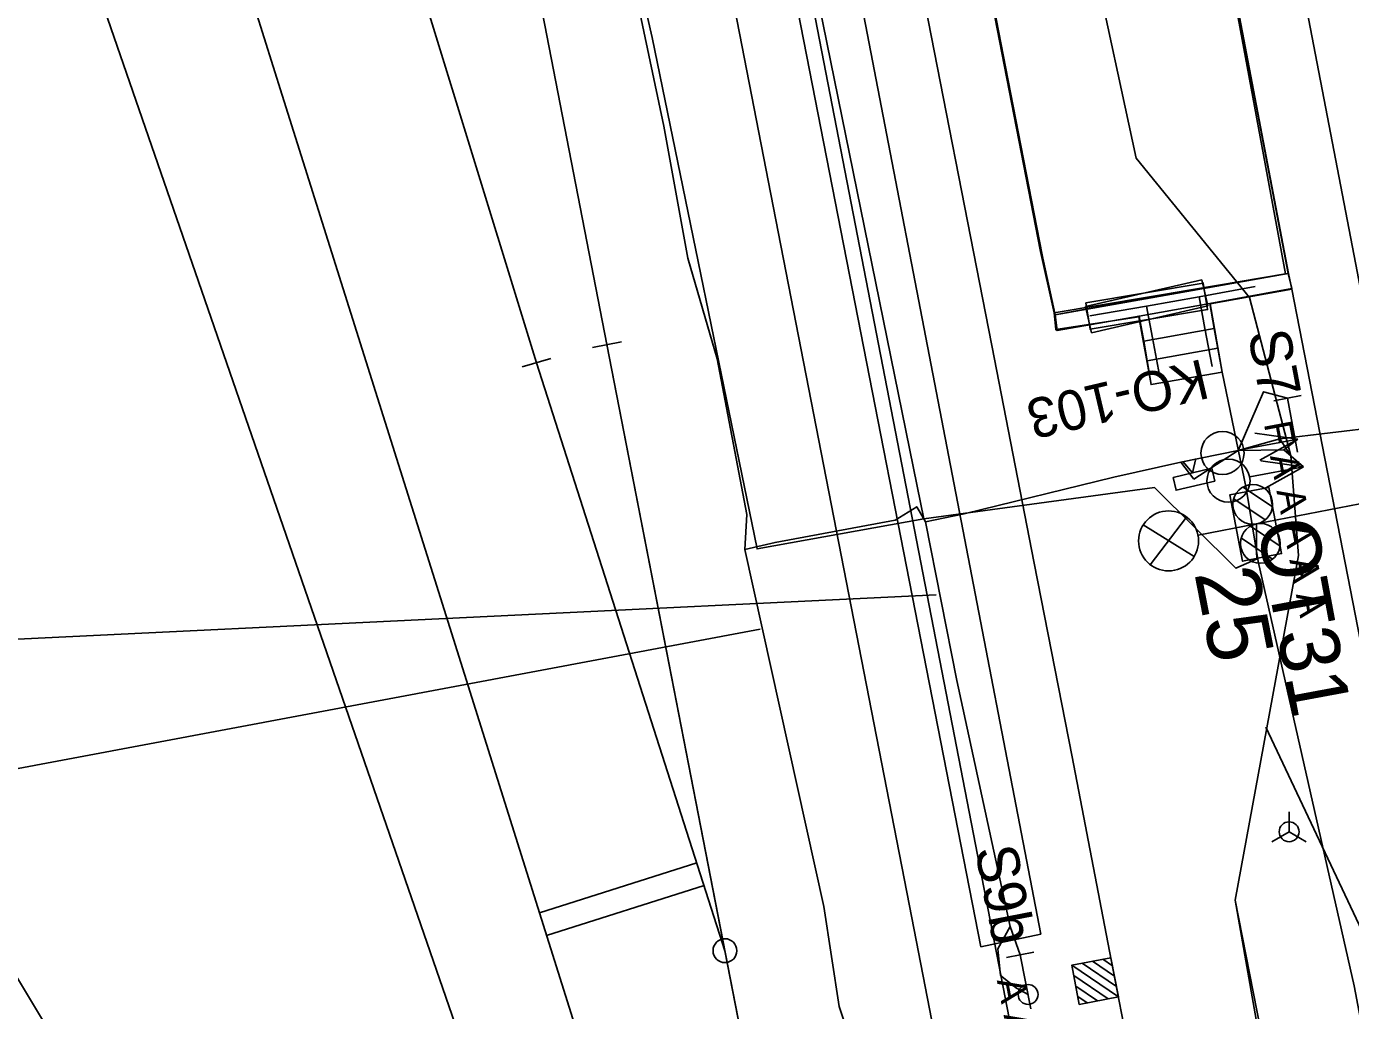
# Model space of a CAD drawing. Extents: x -545736 to -544888, y -1122892 to -1119128.
# Drawn here: x -545168.18 to -545134.88, y -1122258.5 to -1122233.75 of the extents above; entities that cross this region are included whole.
import ezdxf

# ---------------------------------------------------------------- set-up
doc = ezdxf.new("R2010")
doc.units = 0
for name, color, linetype in [('osvětlené plochy-hodnota-obrys', 7, 'Continuous'), ('Podbarveni_Nastupiste', 7, 'Continuous'), ('Vrstva 1', 7, 'Continuous'), ('Vrstva 1 - Koleje', 7, 'Continuous'), ('Vrstva 11 - Trakce', 7, 'Continuous'), ('Vrstva 12 - Trakce zaklady', 7, 'Continuous'), ('Vrstva 13', 7, 'Continuous'), ('Vrstva 14_zastreseni a nastupiste', 7, 'Continuous'), ('Vrstva 16_plochy', 7, 'Continuous'), ('Vrstva 17_ploty - zabradli', 7, 'Continuous'), ('Vrstva 2', 7, 'Continuous'), ('Vrstva 23 - PHS - pozemni - schody - eskalatory', 7, 'Continuous'), ('Vrstva 25', 7, 'Continuous'), ('Vrstva 26', 7, 'Continuous'), ('Vrstva 27', 7, 'Continuous'), ('Vrstva 28 - zabzar', 7, 'Continuous'), ('Vrstva 3 - Lisy - Pocitaci body', 7, 'Continuous'), ('Vrstva 31', 7, 'Continuous'), ('Vrstva 35', 7, 'Continuous'), ('Vrstva 4 - Teren - stezky - prechody - plochy', 7, 'Continuous'), ('Vrstva 6 - Navesti', 7, 'Continuous'), ('Vrstva 63', 7, 'Continuous'), ('Vrstva 7', 7, 'Continuous')]:
    doc.layers.add(name, color=color, linetype=linetype)

msp = doc.modelspace()

# ---------------------------------------------------------------- linework, layer by layer
at = {"layer": 'osvětlené plochy-hodnota-obrys'}
msp.add_lwpolyline([(-545132.033, -1122317.745), (-545201.844, -1121957.194), (-545188.779, -1121954.655), (-545199.189, -1121901.389)], dxfattribs=at)
at = {"layer": 'Podbarveni_Nastupiste'}
for points in [[(-545198.773, -1121951.627), (-545191.691, -1121987.986), (-545182.222, -1122036.609), (-545172.438, -1122086.699), (-545162.999, -1122135.094), (-545153.274, -1122184.937), (-545142.505, -1122240.181), (-545142.306, -1122241.006)], [(-545136.516, -1122239.976), (-545138.799, -1122227.627), (-545147.465, -1122183.189), (-545157.09, -1122133.892), (-545166.638, -1122084.896), (-545171.447, -1122060.234), (-545173.829, -1122047.49), (-545174.717, -1122041.983)], [(-545142.306, -1122241.006), (-545139.39, -1122240.46), (-545136.516, -1122239.976)]]:
    msp.add_lwpolyline(points, dxfattribs=at)
at = {"layer": 'Vrstva 1'}
for points in [[(-545148.11, -1122269.864), (-545153.579, -1122241.752), (-545157.606, -1122221.016), (-545162.537, -1122195.725), (-545168.276, -1122166.312), (-545171.822, -1122147.996)], [(-545134.901, -1122312.911), (-545138.046, -1122296.967), (-545143.24, -1122269.949), (-545145.914, -1122256.175), (-545149.457, -1122237.965), (-545152.971, -1122219.909), (-545157.547, -1122196.44), (-545162.223, -1122172.446), (-545166.848, -1122148.879)], [(-545150.613, -1122256.998), (-545155.352, -1122242.208), (-545159.254, -1122229.505), (-545164.277, -1122213.17), (-545171.316, -1122189.563), (-545175.304, -1122173.781), (-545177.735, -1122161.806)], [(-545144.042, -1122290.699), (-545148.294, -1122278.255), (-545152.413, -1122265.168), (-545157.625, -1122248.574), (-545161.751, -1122235.479), (-545164.693, -1122226.098), (-545170.107, -1122208.853), (-545174.307, -1122195.178), (-545174.307, -1122195.178), (-545179.326, -1122176.026), (-545182.038, -1122162.981)], [(-545137.784, -1122322.523), (-545141.85, -1122311.027), (-545145.756, -1122300.605), (-545151.826, -1122286.809), (-545158.816, -1122273.694), (-545169.453, -1122255.952), (-545171.427, -1122252.524)]]:
    msp.add_lwpolyline(points, dxfattribs=at)
at = {"layer": 'Vrstva 1 - Koleje'}
for points in [[(-545176.383, -1122075.263), (-545174.481, -1122085.012), (-545172.568, -1122094.81), (-545170.661, -1122104.603), (-545170.158, -1122107.18), (-545168.724, -1122114.524), (-545166.809, -1122124.368), (-545164.912, -1122134.097), (-545162.998, -1122143.914), (-545161.094, -1122153.659), (-545159.194, -1122163.404), (-545157.278, -1122173.216), (-545155.337, -1122183.16), (-545153.457, -1122192.791), (-545151.544, -1122202.612), (-545149.632, -1122212.391), (-545147.716, -1122222.215), (-545145.801, -1122232.042), (-545143.903, -1122241.777), (-545142.834, -1122247.253), (-545141.885, -1122252.118), (-545140.814, -1122257.667), (-545140.289, -1122260.383)], [(-545142.334, -1122200.685), (-545140.419, -1122210.525), (-545138.503, -1122220.353), (-545136.566, -1122230.271), (-545134.71, -1122239.954), (-545133.946, -1122244.067), (-545133.443, -1122246.77), (-545131.615, -1122256.726), (-545129.899, -1122266.071), (-545129.007, -1122270.907), (-545127.892, -1122277.019), (-545124.281, -1122296.703), (-545123.116, -1122309.448)]]:
    msp.add_lwpolyline(points, dxfattribs=at)
at = {"layer": 'Vrstva 11 - Trakce'}
for p, q in [((-545137.244, -1122246.262), (-545105.83, -1122240.196)), ((-545137.585, -1122245.337), (-545136.845, -1122245.836)), ((-545137.817, -1122245.633), (-545137.031, -1122246.163)), ((-545137.396, -1122246.321), (-545136.654, -1122246.821)), ((-545137.627, -1122246.619), (-545136.842, -1122247.146))]:
    msp.add_line(p, q, dxfattribs=at)
for centre in [(-545137.34, -1122245.771), (-545137.148, -1122246.753)]:
    msp.add_circle(centre, 0.5, dxfattribs=at)
at = {"layer": 'Vrstva 12 - Trakce zaklady'}
for p, q in [((-545137.92, -1122245.535), (-545136.939, -1122245.343)), ((-545136.614, -1122247.008), (-545137.595, -1122247.2))]:
    msp.add_line(p, q, dxfattribs=at)
for points in [[(-545136.939, -1122245.343), (-545136.614, -1122247.008), (-545137.595, -1122247.2), (-545137.92, -1122245.535), (-545136.939, -1122245.343)], [(-545137.92, -1122245.535), (-545137.92, -1122245.535), (-545137.595, -1122247.2), (-545137.595, -1122247.2)], [(-545136.939, -1122245.343), (-545136.939, -1122245.343), (-545136.614, -1122247.008), (-545136.614, -1122247.008)]]:
    msp.add_lwpolyline(points, dxfattribs=at)
at = {"layer": 'Vrstva 13'}
for p, q in [((-545136.447, -1122239.964), (-545136.443, -1122239.964)), ((-545136.355, -1122240.354), (-545136.356, -1122240.337)), ((-545142.306, -1122241.006), (-545142.337, -1122240.955)), ((-545142.292, -1122241.376), (-545142.261, -1122241.397))]:
    msp.add_line(p, q, dxfattribs=at)
msp.add_lwpolyline([(-545139.377, -1122240.485), (-545142.306, -1122241.006), (-545142.261, -1122241.397), (-545140.197, -1122241.033), (-545138.421, -1122240.72), (-545136.356, -1122240.337), (-545136.447, -1122239.964)], close=True, dxfattribs=at)
for points in [[(-545138.421, -1122240.72), (-545138.41, -1122240.724), (-545136.355, -1122240.354), (-545136.443, -1122239.964)], [(-545142.337, -1122240.955), (-545142.292, -1122241.376), (-545140.203, -1122241.053), (-545140.197, -1122241.033)]]:
    msp.add_lwpolyline(points, dxfattribs=at)
at = {"layer": 'Vrstva 14_zastreseni a nastupiste'}
for p, q in [((-545136.443, -1122239.964), (-545136.447, -1122239.964)), ((-545142.337, -1122240.955), (-545142.306, -1122241.006))]:
    msp.add_line(p, q, dxfattribs=at)
for points in [[(-545174.372, -1122076.877), (-545172.469, -1122086.648), (-545170.563, -1122096.424), (-545168.648, -1122106.251), (-545166.742, -1122116.03), (-545164.832, -1122125.805), (-545162.92, -1122135.608), (-545161.017, -1122145.366), (-545159.102, -1122155.184), (-545157.19, -1122164.981), (-545155.268, -1122174.806), (-545153.362, -1122184.59), (-545151.463, -1122194.367), (-545149.557, -1122204.15), (-545147.636, -1122213.972), (-545145.723, -1122223.752), (-545143.824, -1122233.506), (-545142.674, -1122239.408), (-545142.337, -1122240.955)], [(-545174.341, -1122076.928), (-545172.438, -1122086.699), (-545170.532, -1122096.475), (-545168.617, -1122106.302), (-545166.711, -1122116.081), (-545164.801, -1122125.856), (-545162.889, -1122135.659), (-545160.986, -1122145.417), (-545159.071, -1122155.235), (-545157.159, -1122165.032), (-545155.237, -1122174.857), (-545153.331, -1122184.641), (-545151.432, -1122194.418), (-545149.526, -1122204.201), (-545147.605, -1122214.023), (-545145.692, -1122223.803), (-545143.793, -1122233.557), (-545142.643, -1122239.459), (-545142.306, -1122241.006)], [(-545142.306, -1122241.006), (-545139.377, -1122240.485), (-545136.447, -1122239.964), (-545138.244, -1122230.551), (-545140.147, -1122220.747), (-545142.055, -1122210.937), (-545143.965, -1122201.145), (-545145.873, -1122191.373), (-545147.779, -1122181.574), (-545149.696, -1122171.781), (-545151.614, -1122161.976), (-545153.523, -1122152.193), (-545155.434, -1122142.369), (-545156.586, -1122136.479), (-545158.487, -1122126.724), (-545160.396, -1122116.93), (-545162.308, -1122107.103), (-545164.211, -1122097.329), (-545166.122, -1122087.54), (-545168.031, -1122077.749)], [(-545142.337, -1122240.955), (-545136.443, -1122239.964), (-545138.231, -1122230.556), (-545140.134, -1122220.752), (-545142.042, -1122210.942), (-545143.952, -1122201.15), (-545145.86, -1122191.378), (-545147.766, -1122181.579), (-545149.683, -1122171.786), (-545151.601, -1122161.981), (-545153.51, -1122152.198), (-545155.421, -1122142.374), (-545156.573, -1122136.484), (-545158.474, -1122126.729), (-545160.383, -1122116.935), (-545162.295, -1122107.108), (-545164.198, -1122097.334), (-545166.109, -1122087.545), (-545168.018, -1122077.754)]]:
    msp.add_lwpolyline(points, dxfattribs=at)
at = {"layer": 'Vrstva 16_plochy'}
msp.add_lwpolyline([(-545143.965, -1122201.145), (-545142.055, -1122210.937), (-545140.147, -1122220.747), (-545138.244, -1122230.551), (-545136.447, -1122239.964), (-545139.377, -1122240.485), (-545142.306, -1122241.006), (-545142.643, -1122239.459), (-545143.793, -1122233.557), (-545145.692, -1122223.803), (-545147.605, -1122214.023), (-545149.526, -1122204.201)], dxfattribs=at)
at = {"layer": 'Vrstva 17_ploty - zabradli'}
for p, q in [((-545140.008, -1122240.787), (-545138.691, -1122240.547)), ((-545138.691, -1122240.547), (-545137.282, -1122240.291)), ((-545141.434, -1122241.029), (-545140.008, -1122240.787))]:
    msp.add_line(p, q, dxfattribs=at)
for points in [[(-545138.357, -1122242.305), (-545138.545, -1122241.343), (-545138.691, -1122240.547)], [(-545140.008, -1122240.787), (-545139.86, -1122241.584), (-545139.687, -1122242.517)]]:
    msp.add_lwpolyline(points, dxfattribs=at)
at = {"layer": 'Vrstva 2'}
for p, q in [((-545153.211, -1122241.68), (-545153.947, -1122241.824)), ((-545155.713, -1122242.311), (-545154.991, -1122242.105)), ((-545150.613, -1122256.998), (-545155.352, -1122242.208))]:
    msp.add_line(p, q, dxfattribs=at)
msp.add_lwpolyline([(-545148.11, -1122269.864), (-545150.613, -1122256.998), (-545153.579, -1122241.752)], dxfattribs=at)
msp.add_circle((-545150.613, -1122256.998), 0.3, dxfattribs=at)
at = {"layer": 'Vrstva 23 - PHS - pozemni - schody - eskalatory'}
for p, q in [((-545138.41, -1122240.724), (-545138.421, -1122240.72)), ((-545140.079, -1122241.663), (-545138.307, -1122241.343))]:
    msp.add_line(p, q, dxfattribs=at)
for points in [[(-545141.392, -1122241.453), (-545141.543, -1122240.795), (-545138.624, -1122240.123), (-545138.472, -1122240.781)], [(-545141.541, -1122240.701), (-545141.429, -1122241.368), (-545138.475, -1122240.871), (-545138.587, -1122240.204)]]:
    msp.add_lwpolyline(points, close=True, dxfattribs=at)
for points in [[(-545138.41, -1122240.724), (-545138.109, -1122242.449), (-545139.898, -1122242.758), (-545140.203, -1122241.053)], [(-545138.109, -1122242.449), (-545138.307, -1122241.343), (-545138.421, -1122240.72), (-545140.197, -1122241.033)], [(-545139.898, -1122242.758), (-545140.079, -1122241.663), (-545140.197, -1122241.033), (-545140.203, -1122241.053)], [(-545139.996, -1122242.163), (-545138.217, -1122241.843)]]:
    msp.add_lwpolyline(points, dxfattribs=at)
at = {"layer": 'Vrstva 25'}
for p, q in [((-545139.916, -1122247.289), (-545139.003, -1122246.089)), ((-545140.095, -1122246.289), (-545138.811, -1122247.081)), ((-545138.716, -1122246.549), (-545137.244, -1122246.262))]:
    msp.add_line(p, q, dxfattribs=at)
msp.add_circle((-545139.457, -1122246.691), 0.754, dxfattribs=at)
at = {"layer": 'Vrstva 26'}
for points in [[(-545155.064, -1122220.881), (-545155.129, -1122222.319), (-545152.44, -1122234.026), (-545149.806, -1122246.893), (-545145.608, -1122246.135), (-545139.808, -1122245.349), (-545137.763, -1122247.379), (-545137.229, -1122247.143), (-545137.25, -1122247.012), (-545137.244, -1122246.262)], [(-545170.317, -1122221.476), (-545155.427, -1122264.551), (-545158.826, -1122266.782), (-545159.569, -1122267.253)], [(-545125.523, -1122226.836), (-545126.199, -1122227.617), (-545126.923, -1122226.469), (-545128.585, -1122223.338), (-545130.219, -1122223.203), (-545149.701, -1122226.017), (-545149.372, -1122227.635), (-545145.776, -1122245.312), (-545145.608, -1122246.135)], [(-545149.806, -1122246.893), (-545145.608, -1122246.135), (-545139.808, -1122245.349)]]:
    msp.add_lwpolyline(points, dxfattribs=at)
at = {"layer": 'Vrstva 27'}
for p, q in [((-545139.344, -1122245.096), (-545139.342, -1122245.092)), ((-545142.985, -1122258.125), (-545142.995, -1122258.075))]:
    msp.add_line(p, q, dxfattribs=at)
msp.add_lwpolyline([(-545139.345, -1122245.093), (-545138.372, -1122244.863), (-545138.295, -1122245.187), (-545139.268, -1122245.417)], close=True, dxfattribs=at)
msp.add_lwpolyline([(-545139.097, -1122244.692), (-545138.858, -1122244.978), (-545138.773, -1122244.615)], dxfattribs=at)
msp.add_circle((-545142.99, -1122258.1), 0.25, dxfattribs=at)
at = {"layer": 'Vrstva 28 - zabzar'}
for points in [[(-545136.66, -1122244.12), (-545132.86, -1122243.67), (-545132.22, -1122243.53), (-545132.12, -1122242.5), (-545134.24, -1122231), (-545136.38, -1122218.29), (-545140.4, -1122198.68), (-545141.27, -1122195.81), (-545142.27, -1122190.49), (-545142.25, -1122189.04)], [(-545150.11, -1122246.91), (-545150.06, -1122246.03), (-545150.81, -1122242.11), (-545151.55, -1122239.58), (-545152.15, -1122236.26), (-545155.02, -1122222.67), (-545156.42, -1122214.38), (-545156.49, -1122213.25), (-545157.57, -1122213.47), (-545160.52, -1122214.03), (-545161.23, -1122214.25), (-545161.34, -1122214.32), (-545162.06, -1122212.43), (-545162.9, -1122212.46), (-545165.73, -1122213.33), (-545166.24, -1122213.79), (-545165.3, -1122217.45), (-545164.96, -1122218.08)], [(-545137.71, -1122244.42), (-545137.07, -1122242.94), (-545136.47, -1122243.1)], [(-545131.71, -1122320.28), (-545130.72, -1122320.03), (-545127.65, -1122319.68), (-545126.87, -1122319.51), (-545127.17, -1122313.73), (-545127.74, -1122310.03), (-545128.49, -1122305.02), (-545132.37, -1122285.71), (-545134.29, -1122275.4), (-545134.91, -1122272.08), (-545136.78, -1122260.85), (-545137.78, -1122255.73), (-545136.19, -1122247.06), (-545136.38, -1122244.55), (-545136.66, -1122244.12), (-545137.71, -1122244.42), (-545138.82, -1122245.14)], [(-545136.21, -1122244.13), (-545136.56, -1122244.4), (-545136.06, -1122244.83)], [(-545136.56, -1122244.4), (-545137.71, -1122244.42), (-545139.15, -1122244.71), (-545138.82, -1122245.14)], [(-545139.15, -1122244.71), (-545140.83, -1122245.09), (-545144.6, -1122246.01), (-545145.57, -1122246.21), (-545144.78, -1122250.2), (-545143.44, -1122256.39), (-545143.19, -1122257.1)], [(-545150.11, -1122246.91), (-545149.35, -1122246.73), (-545146.33, -1122246.17), (-545145.79, -1122245.83), (-545145.57, -1122246.21)], [(-545141.57, -1122290.88), (-545141.38, -1122290.28), (-545143, -1122281.41), (-545145.18, -1122271.46), (-545145.33, -1122269.01), (-545146.2, -1122265.17), (-545146.96, -1122260.73), (-545147.74, -1122258.4), (-545148.13, -1122255.89), (-545150.11, -1122246.91)], [(-545143.44, -1122256.39), (-545143.75, -1122256.95), (-545143.68, -1122257.62), (-545143.28, -1122257.94), (-545142.99, -1122258.1)]]:
    msp.add_lwpolyline(points, dxfattribs=at)
at = {"layer": 'Vrstva 3 - Lisy - Pocitaci body'}
for p, q in [((-545136.21, -1122244.13), (-545137.567, -1122244.382)), ((-545136.21, -1122244.13), (-545137.291, -1122243.98)), ((-545136.21, -1122244.13), (-545137.165, -1122244.658)), ((-545136.06, -1122244.83), (-545137.417, -1122245.08)), ((-545136.06, -1122244.83), (-545137.14, -1122244.679)), ((-545136.06, -1122244.83), (-545137.015, -1122245.357)), ((-545136.426, -1122254.007), (-545136.426, -1122253.507)), ((-545136.426, -1122254.007), (-545136.859, -1122254.257)), ((-545136.426, -1122254.007), (-545135.993, -1122254.257)), ((-545141.11, -1122257.215), (-545140.87, -1122257.377)), ((-545141.891, -1122257.366), (-545140.719, -1122258.158)), ((-545141.631, -1122257.316), (-545140.769, -1122257.898)), ((-545141.37, -1122257.265), (-545140.82, -1122257.637)), ((-545141.84, -1122257.626), (-545140.979, -1122258.208)), ((-545141.79, -1122257.887), (-545141.24, -1122258.259)), ((-545141.74, -1122258.147), (-545141.5, -1122258.309))]:
    msp.add_line(p, q, dxfattribs=at)
msp.add_lwpolyline([(-545140.909, -1122257.176), (-545140.719, -1122258.158), (-545141.701, -1122258.348), (-545141.891, -1122257.366)], close=True, dxfattribs=at)
for centre, radius in [((-545138.1, -1122244.479), 0.542), ((-545137.951, -1122245.177), 0.542), ((-545136.426, -1122254.007), 0.25)]:
    msp.add_circle(centre, radius, dxfattribs=at)
at = {"layer": 'Vrstva 31'}
for points in [[(-545141.2, -1122230.63), (-545141.59, -1122230.77), (-545141.35, -1122232.04), (-545140.27, -1122237.06), (-545137.42, -1122240.57), (-545136.38, -1122244.55), (-545136.19, -1122247.06), (-545137.78, -1122255.73), (-545134.91, -1122272.08), (-545134.37, -1122274.99), (-545131.38, -1122275.36), (-545123.37, -1122274.09), (-545122.43, -1122272.99), (-545123.22, -1122267.88), (-545123.52, -1122265.67), (-545122.708, -1122265.909), (-545101.39, -1122261.81), (-545100.97, -1122261.92), (-545101.39, -1122262.57), (-545101.35, -1122263.26), (-545100.46, -1122269.21), (-545099.75, -1122273.09), (-545098.56, -1122275.85), (-545097.66, -1122283.01)], [(-545101.39, -1122261.81), (-545122.708, -1122265.909), (-545123.08, -1122265.98), (-545123.761, -1122273.663), (-545130.676, -1122275.086), (-545130.943, -1122275.373), (-545130.574, -1122274.537), (-545132.583, -1122262.039), (-545133.245, -1122259.348), (-545137.011, -1122251.372)], [(-545137.011, -1122251.372), (-545133.245, -1122259.348), (-545132.583, -1122262.039), (-545130.574, -1122274.537), (-545130.943, -1122275.373), (-545130.676, -1122275.086), (-545123.761, -1122273.663), (-545123.402, -1122266.011), (-545122.708, -1122265.909), (-545101.39, -1122261.81), (-545101.528, -1122261.609)]]:
    msp.add_lwpolyline(points, dxfattribs=at)
at = {"layer": 'Vrstva 35'}
for p, q in [((-545144.6, -1122246.01), (-545140.83, -1122245.09)), ((-545149.35, -1122246.73), (-545146.33, -1122246.17))]:
    msp.add_line(p, q, dxfattribs=at)
at = {"layer": 'Vrstva 4 - Teren - stezky - prechody - plochy'}
for points in [[(-545202.565, -1121956.903), (-545201.056, -1121956.644), (-545199.526, -1121965.043), (-545191.386, -1122006.433), (-545183.698, -1122046.146), (-545176.813, -1122081.324), (-545170.865, -1122111.978), (-545164.201, -1122145.846), (-545158.369, -1122175.606), (-545150.392, -1122216.501), (-545142.671, -1122256.585), (-545144.174, -1122256.905)], [(-545202.565, -1121956.903), (-545200.961, -1121965.123), (-545192.99, -1122006.271), (-545185.214, -1122046.565), (-545178.591, -1122080.816), (-545172.231, -1122113.527), (-545166.05, -1122145.218), (-545159.636, -1122177.662), (-545152.008, -1122216.815), (-545144.174, -1122256.905)], [(-545143.952, -1122201.15), (-545142.042, -1122210.942), (-545140.134, -1122220.752), (-545138.231, -1122230.556), (-545136.443, -1122239.964), (-545136.355, -1122240.354), (-545138.41, -1122240.724), (-545138.109, -1122242.449), (-545139.898, -1122242.758), (-545140.203, -1122241.053), (-545142.292, -1122241.376), (-545142.337, -1122240.955), (-545142.674, -1122239.408), (-545143.824, -1122233.506), (-545145.723, -1122223.752), (-545147.636, -1122213.972), (-545149.557, -1122204.15)], [(-545123.517, -1122364.601), (-545124.466, -1122348.964), (-545125.458, -1122338.104), (-545127.29, -1122323.298), (-545126.412, -1122315.029), (-545125.745, -1122313.441), (-545127.424, -1122298.636), (-545130.054, -1122282.825), (-545134.787, -1122257.879), (-545137.203, -1122247.21), (-545137.508, -1122245.363), (-545138.109, -1122242.449), (-545138.41, -1122240.724), (-545136.355, -1122240.354)], [(-545121.396, -1122364.457), (-545121.715, -1122349.729), (-545122.506, -1122335.393), (-545123.254, -1122325.065), (-545124.429, -1122313.28), (-545125.788, -1122299.621), (-545128.668, -1122281.429), (-545132.975, -1122257.739), (-545136.355, -1122240.354)]]:
    msp.add_lwpolyline(points, dxfattribs=at)
at = {"layer": 'Vrstva 6 - Navesti'}
for p, q in [((-545136.126, -1122243.036), (-545136.814, -1122243.164)), ((-545136.215, -1122244.462), (-545136.47, -1122243.1)), ((-545142.846, -1122257.033), (-545143.534, -1122257.167)), ((-545142.924, -1122258.46), (-545143.19, -1122257.1))]:
    msp.add_line(p, q, dxfattribs=at)
at = {"layer": 'Vrstva 63'}
for p, q in [((-545145.303, -1122248.05), (-545192.91, -1122250.343)), ((-545149.73, -1122248.914), (-545191.65, -1122256.778))]:
    msp.add_line(p, q, dxfattribs=at)
at = {"layer": 'Vrstva 7'}
for p, q in [((-545155.279, -1122256.043), (-545151.321, -1122254.787)), ((-545155.099, -1122256.615), (-545151.138, -1122255.358))]:
    msp.add_line(p, q, dxfattribs=at)

# ---------------------------------------------------------------- texts
at = {"layer": 'Vrstva 11 - Trakce'}
msp.add_text('25', height=1.6, rotation=281.045, dxfattribs=at).set_placement((-545138.811, -1122247.5))
at = {"layer": 'Vrstva 25'}
msp.add_text('OT31', height=1.5, rotation=280.5416, dxfattribs=at).set_placement((-545137.244, -1122246.262))
at = {"layer": 'Vrstva 27'}
msp.add_text('KO-103', height=1, rotation=193.2944, dxfattribs=at).set_placement((-545138.607, -1122242.108))
at = {"layer": 'Vrstva 6 - Navesti'}
for s, height, rotation, p in [('S7', 1.05, 280.6865, (-545137.466, -1122241.471)), ('  F A A A A A ', 0.7, 280.6021, (-545137.158, -1122243.229)), ('S9b', 1.05, 281.0101, (-545144.33, -1122254.448)), ('  A A A ', 0.7, 281.0551, (-545143.877, -1122257.234))]:
    msp.add_text(s, height=height, rotation=rotation, dxfattribs=at).set_placement(p)

doc.saveas('drawing.dxf')
